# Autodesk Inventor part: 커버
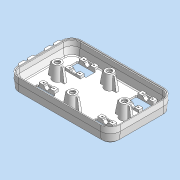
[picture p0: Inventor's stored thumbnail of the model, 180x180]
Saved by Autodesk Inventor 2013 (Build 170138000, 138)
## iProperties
Company: 한국ATC센터
Created: 2015-05
Part Number: 커버
Document SubType Name: 모델링
Designer: KYOUNG IL JANG
Vendor: CBT Solutions
Material: 일반
Author: KYOUNG IL JANG
Comments: 파생
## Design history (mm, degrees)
derived "커버.ipt"
node "솔리드1"
node "솔리드 본체"
node "곡면 본체"
feature "솔리드1::커버.ipt" dims "d0" = 10
tag "피쳐 태그1"
